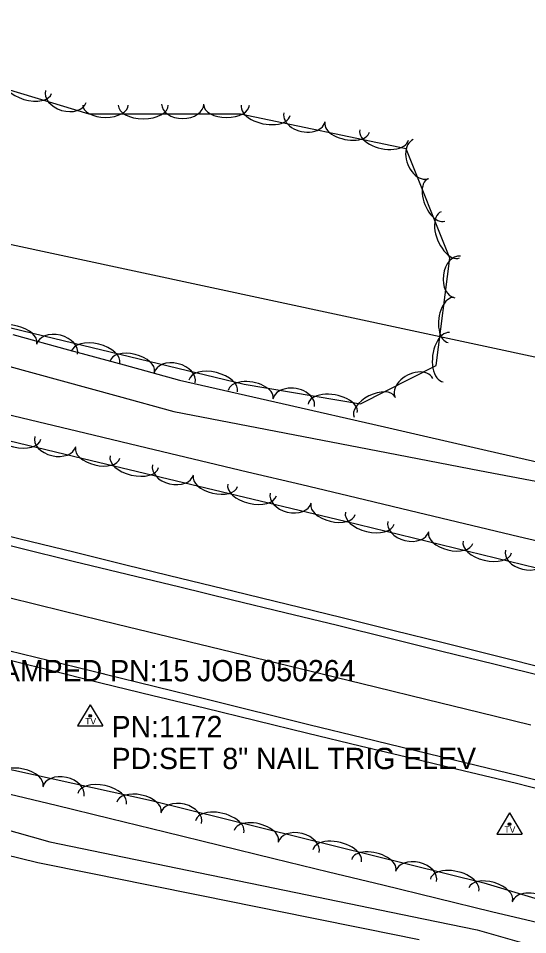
# Model space of a CAD drawing. Extents: x 1441650 to 1491889, y 345904 to 358319.
# Drawn here: x 1457900.1 to 1458019.7, y 351599.3 to 351814.6 of the extents above; entities that cross this region are included whole.
import ezdxf

# ---------------------------------------------------------------- set-up
doc = ezdxf.new("R2010")
doc.units = 0
for name, color, linetype in [('S_DITCHLINE', 7, 'Continuous'), ('S_EDGE_PAVEMENT', 7, 'Continuous'), ('S_PAVEMENT_CROWN', 7, 'Continuous'), ('S_PRIMARY_CTL_ANNOT', 7, 'Continuous'), ('S_SECONDARY_CTL', 7, 'Continuous'), ('S_SECONDARY_CTL_ANNOT', 7, 'Continuous'), ('S_SHOULDER', 7, 'Continuous'), ('S_TREE', 7, 'Continuous'), ('S_WATER_UTILITIES', 7, 'Continuous')]:
    doc.layers.add(name, color=color, linetype=linetype)

msp = doc.modelspace()

# ---------------------------------------------------------------- linework, layer by layer
at = {"layer": 'S_DITCHLINE'}
for points in [[(1457693.87, 351778.58), (1457693.26, 351768.86), (1457712.04, 351764.08), (1457722.22, 351778.1), (1457735.89, 351774.71), (1457749.56, 351771.33), (1457763.24, 351767.94), (1457776.91, 351764.56), (1457790.58, 351761.17), (1457804.25, 351757.79), (1457817.93, 351754.41), (1457831.6, 351751.02), (1457844.72, 351747.43), (1457857.85, 351743.83), (1457870.98, 351740.24), (1457884.1, 351736.64), (1457897.23, 351733.05), (1457910.35, 351729.45), (1457923.48, 351725.86), (1457936.6, 351722.26), (1457960.54, 351717.64), (1457984.48, 351713.03), (1458008.41, 351708.41), (1458032.35, 351703.8)], [(1457898.75, 351740.34), (1457911.81, 351736.76), (1457924.88, 351733.18), (1457937.94, 351729.61), (1457962.01, 351724.11), (1457986.07, 351718.61), (1458010.14, 351713.1), (1458034.21, 351707.6)], [(1457659.44, 351675.18), (1457673.88, 351671.2), (1457688.33, 351667.22), (1457702.77, 351663.25), (1457716.31, 351660.24), (1457729.85, 351657.24), (1457743.39, 351654.23), (1457756.92, 351651.23), (1457770.46, 351648.22), (1457784, 351645.22), (1457797.54, 351642.22), (1457811.08, 351639.21), (1457834.47, 351633.47), (1457857.87, 351627.73), (1457881.26, 351621.99), (1457904.65, 351616.25), (1457917.45, 351613.67), (1457930.24, 351611.09), (1457943.04, 351608.5), (1457955.83, 351605.92), (1457968.63, 351603.34), (1457981.42, 351600.76), (1457994.22, 351598.18)], [(1457883.55, 351627.89), (1457907.42, 351621.14), (1457919.97, 351618.56), (1457932.51, 351615.98), (1457945.06, 351613.39), (1457957.61, 351610.81), (1457970.16, 351608.23), (1457982.7, 351605.64), (1457995.25, 351603.06), (1458007.8, 351600.48), (1458019.92, 351596.98)]]:
    msp.add_lwpolyline(points, dxfattribs=at)
at = {"layer": 'S_EDGE_PAVEMENT'}
for points in [[(1457887.63, 351693.3), (1457900.29, 351690.2), (1457912.95, 351687.11), (1457925.61, 351684.01), (1457937.97, 351681.01), (1457950.33, 351678.01), (1457962.69, 351675.01), (1457975.06, 351672.01), (1457987.3, 351668.98), (1457999.54, 351665.96), (1458011.78, 351662.93), (1458024.02, 351659.9)], [(1457894.49, 351666.86), (1457907.34, 351663.73), (1457920.18, 351660.59), (1457920.15, 351660.6), (1457944.38, 351654.62), (1457968.62, 351648.65), (1457980.87, 351645.67), (1457993.11, 351642.69), (1458005.35, 351639.71), (1458017.6, 351636.73), (1458029.83, 351633.69)]]:
    msp.add_lwpolyline(points, dxfattribs=at)
at = {"layer": 'S_PAVEMENT_CROWN'}
msp.add_lwpolyline([(1457897.8, 351678.54), (1457910.52, 351675.41), (1457923.25, 351672.28), (1457947.51, 351666.39), (1457971.77, 351660.49), (1457983.94, 351657.53), (1457996.12, 351654.57), (1458008.29, 351651.61), (1458020.46, 351648.64)], dxfattribs=at)
at = {"layer": 'S_SECONDARY_CTL'}
for p, q in [((1457916.96, 351653.33), (1457913.95, 351648.38)), ((1457916.96, 351653.33), (1457919.91, 351648.38)), ((1457913.95, 351648.38), (1457919.91, 351648.38)), ((1458015.44, 351627.92), (1458012.43, 351622.96)), ((1458015.44, 351627.92), (1458018.39, 351622.96)), ((1458012.43, 351622.96), (1458018.39, 351622.96))]:
    msp.add_line(p, q, dxfattribs=at)
for centre, radius in [((1457916.96, 351650.72), 0.311), ((1457916.96, 351650.72), 0.183), ((1457916.96, 351650.72), 0.103), ((1458015.44, 351625.3), 0.311), ((1458015.44, 351625.3), 0.183), ((1458015.44, 351625.3), 0.103)]:
    msp.add_circle(centre, radius, dxfattribs=at)
at = {"layer": 'S_SHOULDER'}
for points in [[(1457887.94, 351695.43), (1457900.5, 351692.34), (1457913.06, 351689.25), (1457925.62, 351686.16), (1457938.17, 351683.09), (1457950.73, 351680.03), (1457963.28, 351676.96), (1457975.83, 351673.9), (1457988, 351670.87), (1458000.17, 351667.85), (1458012.34, 351664.82), (1458024.51, 351661.8)], [(1457893.92, 351664.87), (1457906.69, 351661.69), (1457919.46, 351658.52), (1457931.62, 351655.55), (1457943.77, 351652.59), (1457955.92, 351649.62), (1457968.07, 351646.66), (1457980.32, 351643.72), (1457992.57, 351640.79), (1458004.82, 351637.85), (1458017.08, 351634.92), (1458029.31, 351631.81)]]:
    msp.add_lwpolyline(points, dxfattribs=at)
at = {"layer": 'S_TREE'}
for points in [[(1458063.5, 351675.22), (1457976.8, 351696.4), (1457915.32, 351711.13), (1457845.37, 351727.99), (1457795.65, 351739.56), (1457750.24, 351750.51), (1457706.5, 351763.56), (1457712.61, 351774.74), (1457736.67, 351783.94), (1457764.89, 351777.17), (1457812.74, 351765.63), (1457835.56, 351754.37), (1457870.07, 351748.7), (1457908.34, 351739.47), (1457953.11, 351728.68), (1457980.43, 351724.02), (1457998.19, 351733.08), (1458001.42, 351758.29), (1457991.14, 351783.93), (1457952.22, 351792.08), (1457916.66, 351792.11), (1457887.9, 351800.76), (1457868.64, 351830.86)], [(1457890.15, 351723.3), (1457902.89, 351720.26), (1457915.64, 351717.22), (1457928.38, 351714.18), (1457941.13, 351711.14), (1457953.87, 351708.1), (1457966.62, 351705.06), (1457979.37, 351702.02), (1457992.11, 351698.98), (1458004.86, 351695.94), (1458017.6, 351692.9), (1458030.35, 351689.86)], [(1457890.15, 351723.3), (1457902.89, 351720.26), (1457915.64, 351717.22), (1457928.38, 351714.18), (1457941.13, 351711.14), (1457953.87, 351708.1), (1457966.62, 351705.06), (1457979.37, 351702.02), (1457992.11, 351698.98), (1458004.86, 351695.94), (1458017.6, 351692.9), (1458030.35, 351689.86)], [(1457821.5, 351595.5), (1457787.41, 351603.72), (1457753.76, 351611.83), (1457727.3, 351627.82), (1457724.37, 351641.23), (1457738.27, 351643.36), (1457777.6, 351635.64), (1457828.15, 351621.15), (1457871.08, 351610.75), (1457892.8, 351605.93), (1457897.13, 351615.53), (1457853.36, 351632.84), (1457772.81, 351652.12), (1457733.73, 351657.52), (1457714.5, 351662.28), (1457690.24, 351683.43), (1457699.75, 351688.83), (1457763.7, 351674.07), (1457848.12, 351649.15), (1457931.3, 351630.84), (1458009.37, 351611.48), (1458054.41, 351597.92)], [(1457896.17, 351632.83), (1457908.95, 351629.71), (1457921.73, 351626.59), (1457934.52, 351623.47), (1457947.3, 351620.35), (1457960.09, 351617.24), (1457972.87, 351614.12), (1457985.66, 351611), (1457998.44, 351607.88), (1458011.22, 351604.76), (1458030.13, 351600.27)], [(1457896.17, 351632.83), (1457908.95, 351629.71), (1457921.73, 351626.59), (1457934.52, 351623.47), (1457947.3, 351620.35), (1457960.09, 351617.24), (1457972.87, 351614.12), (1457985.66, 351611), (1457998.44, 351607.88), (1458011.22, 351604.76), (1458030.13, 351600.27)]]:
    msp.add_lwpolyline(points, dxfattribs=at)
for centre, major_axis, ratio, start_param, end_param in [((1457902.26, 351798.66), (5.62, -1.69), 0.550079, 3.141593, 6.283185), ((1457911.2, 351796.24), (4.75, -1.43), 0.68531, 3.141593, 6.283185), ((1457920.54, 351794.23), (5.35, 0), 0.540699, 3.141593, 6.283185), ((1457929.41, 351794.22), (5.87, 0), 0.550079, 3.141593, 6.283185), ((1457938.67, 351794.48), (4.96, 0), 0.68531, 3.141593, 6.283185), ((1457948.97, 351794.21), (5.35, 0), 0.540699, 3.141593, 6.283185), ((1457958.15, 351793.01), (5.74, -1.2), 0.550113, 3.141604, 6.283197), ((1457967.27, 351791.36), (4.85, -1.02), 0.685352, 3.141612, 6.283205), ((1457977.3, 351789), (5.23, -1.1), 0.540732, 3.141604, 6.283197), ((1457985.97, 351787.18), (5.74, -1.2), 0.550113, 3.141604, 6.283197), ((1457994.66, 351781.54), (1.84, -4.58), 0.688732, 3.141554, 6.283147), ((1457998.23, 351771.93), (1.98, -4.94), 0.543399, 3.14157, 6.283163), ((1458001.52, 351763.75), (2.18, -5.42), 0.552826, 3.141569, 6.283162), ((1458003.25, 351753.84), (-0.63, -4.88), 0.689575, 3.141658, 6.28325), ((1458001.69, 351743.72), (-0.68, -5.27), 0.544064, 3.141631, 6.283224), ((1457899.18, 351739.5), (-5.2, 1.25), 0.540699, 3.141593, 6.283185), ((1457909.13, 351736.83), (-4.82, 1.16), 0.68531, 3.141593, 6.283185), ((1458000.57, 351734.98), (-0.74, -5.78), 0.553503, 3.141632, 6.283225), ((1457918.19, 351734.92), (-5.7, 1.38), 0.550079, 3.141593, 6.283185), ((1457926.81, 351732.84), (-5.2, 1.25), 0.540699, 3.141593, 6.283185), ((1457936.77, 351730.17), (-4.82, 1.16), 0.68531, 3.141593, 6.283185), ((1457945.83, 351728.25), (-5.7, 1.38), 0.550079, 3.141593, 6.283185), ((1457992.99, 351727.75), (-4.41, -2.25), 0.686177, 3.141684, 6.283277), ((1457954.62, 351726.27), (-5.27, 0.9), 0.540699, 3.141593, 6.283186), ((1457964.73, 351724.28), (-4.88, 0.83), 0.68531, 3.141593, 6.283186), ((1457973.9, 351722.98), (-5.78, 0.99), 0.550079, 3.141593, 6.283186), ((1457983.71, 351723.31), (-4.76, -2.43), 0.541383, 3.141647, 6.283239), ((1457899.66, 351717.08), (5.7, -1.38), 0.550079, 3.141593, 6.283185), ((1457908.72, 351715.17), (4.82, -1.16), 0.68531, 3.141593, 6.283185), ((1457918.68, 351712.5), (5.2, -1.25), 0.540699, 3.141593, 6.283185), ((1457927.3, 351710.44), (5.71, -1.37), 0.550079, 3.141593, 6.283185), ((1457936.36, 351708.54), (4.82, -1.15), 0.68531, 3.141593, 6.283185), ((1457946.32, 351705.88), (5.2, -1.25), 0.540699, 3.141593, 6.283185), ((1457954.95, 351703.82), (5.71, -1.37), 0.550079, 3.141593, 6.283185), ((1457964.01, 351701.91), (4.82, -1.15), 0.68531, 3.141593, 6.283185), ((1457973.97, 351699.26), (5.2, -1.25), 0.540699, 3.141593, 6.283185), ((1457982.6, 351697.17), (5.7, -1.39), 0.550079, 3.141593, 6.283185), ((1457991.65, 351695.23), (4.81, -1.18), 0.68531, 3.141593, 6.283185), ((1458001.6, 351692.53), (5.19, -1.27), 0.540699, 3.141593, 6.283185), ((1458010.21, 351690.42), (5.7, -1.39), 0.550079, 3.141593, 6.283185), ((1458019.27, 351688.48), (4.81, -1.18), 0.68531, 3.141593, 6.283185), ((1457900.64, 351635.42), (-5.22, 1.15), 0.540397, 3.141593, 6.283185), ((1457910.65, 351632.95), (-4.84, 1.06), 0.684928, 3.141593, 6.283185), ((1457919.74, 351631.21), (-5.73, 1.26), 0.549772, 3.141593, 6.283185), ((1457928.4, 351629.31), (-5.22, 1.15), 0.540397, 3.141593, 6.283185), ((1457938.3, 351626.65), (-4.81, 1.19), 0.684941, 3.141841, 6.283433), ((1457947.35, 351624.68), (-5.7, 1.41), 0.549783, 3.141744, 6.283337), ((1457955.96, 351622.54), (-5.19, 1.29), 0.540407, 3.141739, 6.283332), ((1457965.89, 351619.81), (-4.81, 1.19), 0.684941, 3.141841, 6.283433), ((1457974.94, 351617.84), (-5.7, 1.41), 0.549783, 3.141744, 6.283337), ((1457983.55, 351615.7), (-5.19, 1.29), 0.540407, 3.141739, 6.283332), ((1457993.48, 351612.97), (-4.81, 1.19), 0.684941, 3.141841, 6.283433), ((1458002.53, 351610.99), (-5.7, 1.41), 0.549783, 3.141744, 6.283337), ((1458011.01, 351608.78), (-5.12, 1.54), 0.54041, 3.14173, 6.283322), ((1458020.8, 351605.56), (-4.74, 1.43), 0.684944, 3.141824, 6.283417)]:
    msp.add_ellipse(centre, major_axis=major_axis, ratio=ratio, start_param=start_param, end_param=end_param, dxfattribs=at)
at = {"layer": 'S_WATER_UTILITIES'}
msp.add_line((1456494.84, 352062.52), (1458511.04, 351630.06), dxfattribs=at)

# ---------------------------------------------------------------- texts
at = {"layer": 'S_PRIMARY_CTL_ANNOT'}
msp.add_text('PD:STD AHTD MON.STAMPED PN:15 JOB 050264', height=5, dxfattribs=at).set_placement((1457823.55, 351658.85))
at = {"layer": 'S_SECONDARY_CTL'}
for p in [(1457915.76, 351648.71), (1458014.24, 351623.29)]:
    msp.add_text('TV', height=1.5, rotation=360, dxfattribs=at).set_placement(p)
at = {"layer": 'S_SECONDARY_CTL_ANNOT'}
for s, p in [('PN:1172', (1457921.96, 351645.72)), ('PD:SET 8" NAIL TRIG ELEV', (1457921.96, 351638.22))]:
    msp.add_text(s, height=5, dxfattribs=at).set_placement(p)

doc.saveas('drawing.dxf')
